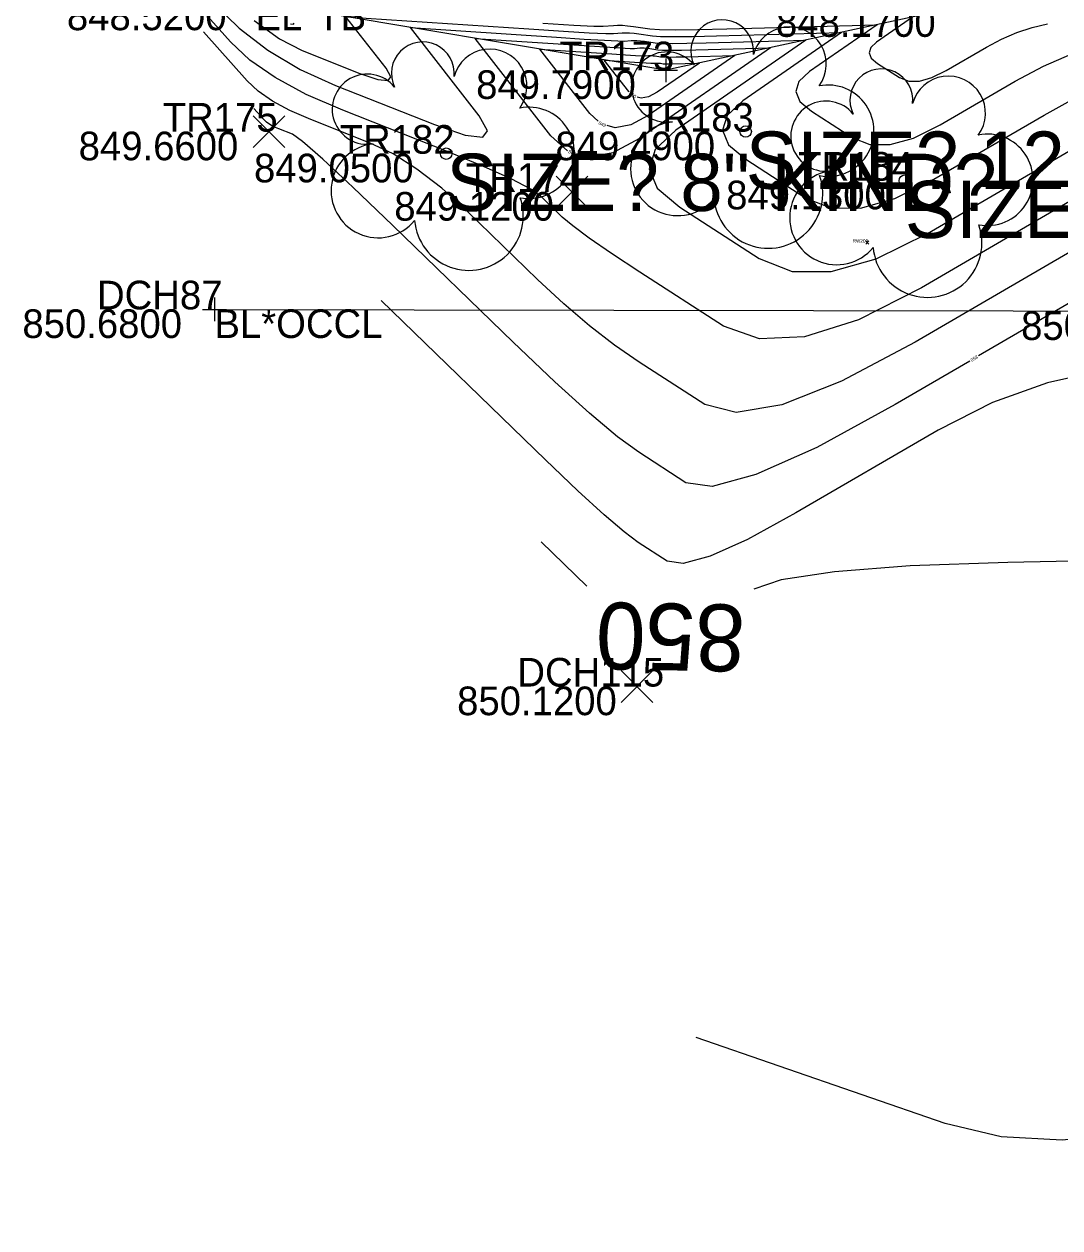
# Model space of a CAD drawing. Extents: x 1654928 to 1810050, y 486881 to 626330.
# Drawn here: x 1801309.2 to 1801352.6, y 489730.2 to 489780.6 of the extents above; entities that cross this region are included whole.
import ezdxf

# ---------------------------------------------------------------- set-up
doc = ezdxf.new("R2010")
doc.units = 0
for name, color, linetype in [('DT_X_Contour_Major', 7, 'Continuous'), ('DT_X_Contour_Minor', 7, 'Continuous'), ('GK_Visualization', 7, 'Continuous'), ('SV_X_Occupation_Line', 7, 'Continuous'), ('SV_X_Random_Point', 7, 'Continuous'), ('SV_X_Shot_Marker', 7, 'Continuous'), ('SV_X_Text_Comment', 7, 'Continuous'), ('SV_X_Text_Elevation', 7, 'Continuous'), ('SV_X_Text_Name', 7, 'Continuous'), ('SV_X_Top_of_Bank', 7, 'Continuous'), ('VG_X_Cells', 7, 'Continuous'), ('VG_X_Text', 7, 'Continuous')]:
    doc.layers.add(name, color=color, linetype=linetype)

msp = doc.modelspace()

# ---------------------------------------------------------------- linework, layer by layer
at = {"layer": 'DT_X_Contour_Major'}
for points in [[(1801317.099, 489781.505), (1801318.166, 489780.452), (1801319.374, 489779.524), (1801320.721, 489778.722), (1801322.208, 489778.046), (1801326.359, 489776.41), (1801327.644, 489775.972), (1801328.385, 489775.887), (1801328.583, 489776.153), (1801328.237, 489776.772), (1801325.354, 489780.479), (1801331.47, 489780.071), (1801332.631, 489779.995), (1801333.49, 489779.944), (1801334.049, 489779.917), (1801334.308, 489779.914), (1801334.596, 489779.937), (1801334.712, 489779.942), (1801334.844, 489779.938), (1801334.992, 489779.926), (1801335.155, 489779.905), (1801335.612, 489779.838), (1801335.874, 489779.819), (1801336.318, 489779.813), (1801336.942, 489779.819), (1801337.748, 489779.838), (1801341.932, 489779.955), (1801336.481, 489776.178), (1801335.615, 489775.369), (1801335.354, 489774.562), (1801335.696, 489773.755), (1801336.642, 489772.949), (1801339.969, 489770.802), (1801341.347, 489770.263), (1801342.983, 489770.258), (1801344.878, 489770.786), (1801347.032, 489771.848), (1801353.12, 489775.39)], [(1801332.738, 489757.079), (1801330.823, 489758.933)], [(1801362.576, 489758.316), (1801350.398, 489758.064), (1801346.297, 489757.921), (1801343.128, 489757.678), (1801340.89, 489757.337), (1801339.752, 489756.954)]]:
    msp.add_lwpolyline(points, dxfattribs=at)
at = {"layer": 'DT_X_Contour_Minor'}
for points in [[(1801354.327, 489773.969), (1801346.771, 489769.573), (1801344.128, 489768.237), (1801341.864, 489767.524), (1801339.981, 489767.436), (1801338.477, 489767.972), (1801334.972, 489770.233), (1801333.783, 489771.013), (1801332.844, 489771.658), (1801332.154, 489772.166), (1801331.714, 489772.539), (1801330.874, 489773.352), (1801330.392, 489773.7), (1801329.573, 489774.136), (1801328.419, 489774.658), (1801326.929, 489775.268), (1801322.509, 489777.01), (1801320.972, 489777.679), (1801319.675, 489778.379), (1801318.619, 489779.11), (1801317.803, 489779.873), (1801314.558, 489783.504)], [(1801318.799, 489780.777), (1801319.854, 489780.008), (1801320.811, 489779.513), (1801323.232, 489778.559), (1801323.982, 489778.303), (1801324.414, 489778.254), (1801324.53, 489778.409), (1801324.328, 489778.77), (1801322.646, 489780.932), (1801330.311, 489780.421), (1801331.765, 489780.327), (1801332.842, 489780.262), (1801333.543, 489780.228), (1801333.867, 489780.224), (1801334.228, 489780.254), (1801334.374, 489780.26), (1801334.539, 489780.255), (1801334.724, 489780.239), (1801334.929, 489780.213), (1801335.501, 489780.129), (1801335.83, 489780.106), (1801336.385, 489780.098), (1801337.168, 489780.106), (1801338.178, 489780.129), (1801343.421, 489780.276), (1801339.284, 489777.41), (1801338.627, 489776.796), (1801338.428, 489776.182), (1801338.687, 489775.57), (1801339.405, 489774.958), (1801341.931, 489773.328), (1801342.977, 489772.92), (1801344.219, 489772.916), (1801345.657, 489773.317), (1801347.292, 489774.123), (1801351.913, 489776.811), (1801353.549, 489777.716)], [(1801320.32, 489780.635), (1801320.443, 489780.62), (1801320.476, 489780.665)], [(1801330.899, 489780.658), (1801332.194, 489780.581), (1801333.037, 489780.54), (1801333.426, 489780.535), (1801333.86, 489780.57), (1801334.035, 489780.577), (1801334.234, 489780.572), (1801334.456, 489780.553), (1801334.702, 489780.522), (1801335.391, 489780.421), (1801335.785, 489780.392), (1801336.453, 489780.383), (1801337.394, 489780.392), (1801338.608, 489780.421), (1801344.91, 489780.598), (1801342.086, 489778.641), (1801341.638, 489778.222), (1801341.502, 489777.803), (1801341.679, 489777.385), (1801342.169, 489776.968), (1801343.893, 489775.855), (1801344.607, 489775.576), (1801345.455, 489775.574), (1801346.436, 489775.847), (1801347.552, 489776.397), (1801350.706, 489778.232), (1801351.892, 489778.863), (1801353.082, 489779.378)], [(1801346.399, 489780.919), (1801344.889, 489779.872), (1801344.649, 489779.648), (1801344.576, 489779.424), (1801344.671, 489779.2), (1801344.933, 489778.977), (1801345.855, 489778.382), (1801346.237, 489778.233), (1801346.69, 489778.231), (1801347.215, 489778.378), (1801347.812, 489778.672), (1801349.499, 489779.654), (1801350.133, 489779.991), (1801350.77, 489780.267), (1801351.41, 489780.481), (1801352.052, 489780.633)], [(1801355.534, 489772.548), (1801346.511, 489767.298), (1801343.422, 489765.659), (1801340.922, 489764.677), (1801339.01, 489764.354), (1801337.687, 489764.688), (1801334.945, 489766.458), (1801333.907, 489767.172), (1801332.851, 489767.987), (1801331.777, 489768.903), (1801330.683, 489769.919), (1801327.744, 489772.765), (1801326.662, 489773.745), (1801325.622, 489774.55), (1801324.623, 489775.181), (1801323.666, 489775.637), (1801321.167, 489776.622), (1801320.298, 489777), (1801319.565, 489777.395), (1801318.968, 489777.809), (1801318.507, 489778.24), (1801316.673, 489780.292)], [(1801331.938, 489775.316), (1801331.235, 489775.944), (1801328.062, 489780.025), (1801332.63, 489779.72), (1801333.496, 489779.664), (1801334.138, 489779.626), (1801334.556, 489779.605), (1801334.749, 489779.603), (1801334.964, 489779.621), (1801335.051, 489779.624), (1801335.149, 489779.621), (1801335.26, 489779.612), (1801335.382, 489779.597), (1801335.723, 489779.547)], [(1801335.723, 489779.547), (1801335.919, 489779.532), (1801336.25, 489779.528), (1801336.716, 489779.533), (1801337.318, 489779.547), (1801340.443, 489779.634), (1801334.949, 489775.827), (1801333.834, 489775.223), (1801332.843, 489775.041), (1801332.331, 489775.183)], [(1801333.226, 489776.554), (1801332.867, 489776.874), (1801330.77, 489779.571), (1801333.789, 489779.37), (1801334.362, 489779.333), (1801334.786, 489779.308), (1801335.062, 489779.294), (1801335.19, 489779.293), (1801335.332, 489779.304), (1801335.39, 489779.306), (1801335.455, 489779.305), (1801335.528, 489779.298), (1801335.608, 489779.288), (1801335.834, 489779.255)], [(1801335.834, 489779.255), (1801335.963, 489779.246), (1801336.182, 489779.243), (1801336.49, 489779.246), (1801336.888, 489779.255), (1801338.954, 489779.313), (1801335.322, 489776.797), (1801334.585, 489776.397), (1801333.93, 489776.277), (1801333.592, 489776.371)], [(1801334.513, 489777.791), (1801334.499, 489777.804), (1801333.477, 489779.118), (1801334.948, 489779.02), (1801335.228, 489779.002), (1801335.434, 489778.989), (1801335.569, 489778.983), (1801335.631, 489778.982), (1801335.7, 489778.988), (1801335.728, 489778.989), (1801335.76, 489778.988), (1801335.795, 489778.985), (1801335.835, 489778.98), (1801335.945, 489778.964)], [(1801335.945, 489778.964), (1801336.008, 489778.959), (1801336.114, 489778.958), (1801336.265, 489778.959), (1801337.465, 489778.992), (1801335.695, 489777.766), (1801335.336, 489777.571), (1801335.017, 489777.513), (1801334.852, 489777.559)], [(1801348.8, 489766.506), (1801345.666, 489764.683), (1801342.387, 489762.889), (1801339.833, 489761.745), (1801338.003, 489761.25), (1801336.898, 489761.405), (1801334.918, 489762.683), (1801334.031, 489763.331), (1801332.859, 489764.316), (1801331.399, 489765.639), (1801329.653, 489767.3), (1801324.614, 489772.178), (1801322.933, 489773.789), (1801321.671, 489774.964), (1801320.827, 489775.703), (1801320.402, 489776.006), (1801319.826, 489776.234), (1801319.625, 489776.321), (1801319.456, 489776.412), (1801319.318, 489776.508), (1801319.212, 489776.607), (1801318.788, 489777.081)], [(1801355.375, 489770.332), (1801349.163, 489766.718)], [(1801367.426, 489766.867), (1801367.065, 489766.756), (1801365.508, 489766.558), (1801363.36, 489766.458), (1801356.846, 489766.323), (1801354.429, 489766.116), (1801352.062, 489765.596), (1801349.745, 489764.762), (1801347.48, 489763.615), (1801341.505, 489760.139), (1801339.487, 489759.035), (1801337.915, 489758.331), (1801336.789, 489758.026), (1801336.109, 489758.121), (1801334.89, 489758.908), (1801334.305, 489759.345), (1801333.465, 489760.066), (1801332.37, 489761.071), (1801331.018, 489762.361), (1801324.117, 489769.041)], [(1801364.269, 489736.561), (1801358.436, 489734.841), (1801355.45, 489734.14), (1801352.677, 489733.859), (1801350.118, 489734), (1801347.773, 489734.563), (1801337.326, 489738.169)]]:
    msp.add_lwpolyline(points, dxfattribs=at)
at = {"layer": 'GK_Visualization'}
for p, q in [((1801344.435, 489771.403), (1801344.569, 489771.536)), ((1801344.435, 489771.536), (1801344.569, 489771.403))]:
    msp.add_line(p, q, dxfattribs=at)
at = {"layer": 'SV_X_Occupation_Line'}
msp.add_lwpolyline([(1801317.131, 489768.671), (1801358.983, 489768.588), (1801397.909, 489769.246), (1801416.492, 489765.323), (1801429.827, 489757.814), (1801441.541, 489745.071), (1801453.578, 489722.317), (1801464.849, 489700.041), (1801476.834, 489674.228), (1801497.657, 489627.098)], dxfattribs=at)
at = {"layer": 'SV_X_Random_Point'}
for p, q in [((1801318.756, 489775.45), (1801320.09, 489776.785)), ((1801318.756, 489776.785), (1801320.09, 489775.45)), ((1801331.46, 489772.919), (1801332.793, 489774.254)), ((1801331.46, 489774.254), (1801332.793, 489772.919)), ((1801334.18, 489752.2), (1801335.513, 489753.535)), ((1801334.18, 489753.535), (1801335.513, 489752.2))]:
    msp.add_line(p, q, dxfattribs=at)
at = {"layer": 'SV_X_Shot_Marker'}
for p, q in [((1801336.05, 489779.187), (1801336.05, 489778.187)), ((1801335.55, 489778.687), (1801336.55, 489778.687)), ((1801336.05, 489778.687), (1801336.05, 489778.687)), ((1801317.131, 489769.171), (1801317.131, 489768.171)), ((1801316.631, 489768.671), (1801317.631, 489768.671)), ((1801317.131, 489768.671), (1801317.131, 489768.671))]:
    msp.add_line(p, q, dxfattribs=at)
at = {"layer": 'SV_X_Top_of_Bank'}
msp.add_lwpolyline([(1801414.708, 489795.331), (1801414.041, 489794.432), (1801412.967, 489794.649), (1801413.875, 489794.726), (1801401.963, 489788.753), (1801387.705, 489783.674), (1801376.875, 489783.007), (1801368.983, 489780.458), (1801361.095, 489781.125), (1801348.111, 489781.288), (1801336.05, 489778.687), (1801318.855, 489781.567)], dxfattribs=at)
at = {"layer": 'VG_X_Cells'}
for centre in [(1801339.405, 489776.119), (1801326.851, 489775.192), (1801346.076, 489774.062)]:
    msp.add_circle(centre, 0.24, dxfattribs=at)
for centre, radius, start, end in [((1801338.421, 489779.487), 1.317, 354.0047, 205.9741), ((1801341.231, 489778.949), 1.553, 323.83, 165.0376), ((1801325.867, 489778.559), 1.317, 354.0047, 205.9741), ((1801328.677, 489778.021), 1.553, 323.83, 165.0376), ((1801336.095, 489777.984), 1.471, 39.0625, 279.5412), ((1801345.093, 489777.429), 1.317, 354.0047, 205.9741), ((1801323.541, 489777.056), 1.471, 39.0625, 279.5412), ((1801347.903, 489776.891), 1.553, 323.83, 165.0376), ((1801342.865, 489776.155), 1.915, 259.1453, 101.4596), ((1801330.311, 489775.228), 1.915, 259.1453, 101.4596), ((1801342.767, 489775.926), 1.471, 39.0625, 279.5412), ((1801336.551, 489774.571), 1.974, 96.1722, 320.5737), ((1801323.997, 489773.643), 1.974, 96.1722, 320.5737), ((1801349.537, 489774.098), 1.915, 259.1453, 101.4596), ((1801340.351, 489773.514), 2.284, 184.9476, 19.4572), ((1801343.223, 489772.513), 1.974, 96.1722, 320.5737), ((1801327.797, 489772.587), 2.284, 184.9476, 19.4572), ((1801347.023, 489771.456), 2.284, 184.9476, 19.4572)]:
    msp.add_arc(centre, radius, start, end, dxfattribs=at)

# ---------------------------------------------------------------- texts
at = {"layer": 'DT_X_Contour_Major'}
msp.add_text('850', height=2.8, rotation=178.9822, dxfattribs=at).set_placement((1801339.399, 489756.289))
at = {"layer": 'DT_X_Contour_Minor'}
for s, rotation, p in [('850', 325.5365, (1801334.494, 489777.687)), ('849', 333.446, (1801333.215, 489776.436)), ('849', 341.2769, (1801331.955, 489775.224)), ('850', 210.1912, (1801349.089, 489766.756))]:
    msp.add_text(s, height=0.14, rotation=rotation, dxfattribs=at).set_placement(p)
at = {"layer": 'GK_Visualization'}
msp.add_text('RW200', height=0.14, dxfattribs=at).set_placement((1801343.89, 489771.47))
at = {"layer": 'SV_X_Text_Comment'}
for s, p in [('EL*TB', (1801318.855, 489780.367)), ('BL*OCCL', (1801317.131, 489767.471))]:
    msp.add_text(s, height=1.2, dxfattribs=at).set_placement(p)
at = {"layer": 'SV_X_Text_Elevation'}
for s, p in [('848.5200', (1801310.947, 489780.367)), ('848.1700', (1801340.676, 489780.088)), ('849.7900', (1801328.104, 489777.487)), ('849.6600', (1801311.439, 489774.917)), ('849.4900', (1801331.43, 489774.919)), ('849.0500', (1801318.791, 489773.992)), ('849.1200', (1801324.672, 489772.387)), ('849.1300', (1801338.585, 489772.862)), ('850.6800', (1801309.081, 489767.471)), ('850.3200', (1801350.952, 489767.388)), ('850.1200', (1801327.307, 489751.667))]:
    msp.add_text(s, height=1.2, dxfattribs=at).set_placement(p)
at = {"layer": 'SV_X_Text_Name'}
for s, p in [('TR173', (1801331.591, 489778.687)), ('TR175', (1801314.964, 489776.117)), ('TR183', (1801334.927, 489776.119)), ('TR182', (1801322.382, 489775.192)), ('TR184', (1801341.608, 489774.062)), ('TR174', (1801327.677, 489773.587)), ('DCH87', (1801312.209, 489768.671)), ('DCH115', (1801329.831, 489752.867))]:
    msp.add_text(s, height=1.2, dxfattribs=at).set_placement(p)
at = {"layer": 'VG_X_Text'}
for s, p in [('SIZE? 12" KIND?', (1801339.405, 489773.72)), ('SIZE? 8" KIND?', (1801326.851, 489772.792)), ('SIZE? 8" KIND?', (1801346.076, 489771.662))]:
    msp.add_text(s, height=2.4, dxfattribs=at).set_placement(p)

doc.saveas('drawing.dxf')
